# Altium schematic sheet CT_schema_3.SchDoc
size 297 x 271 mm
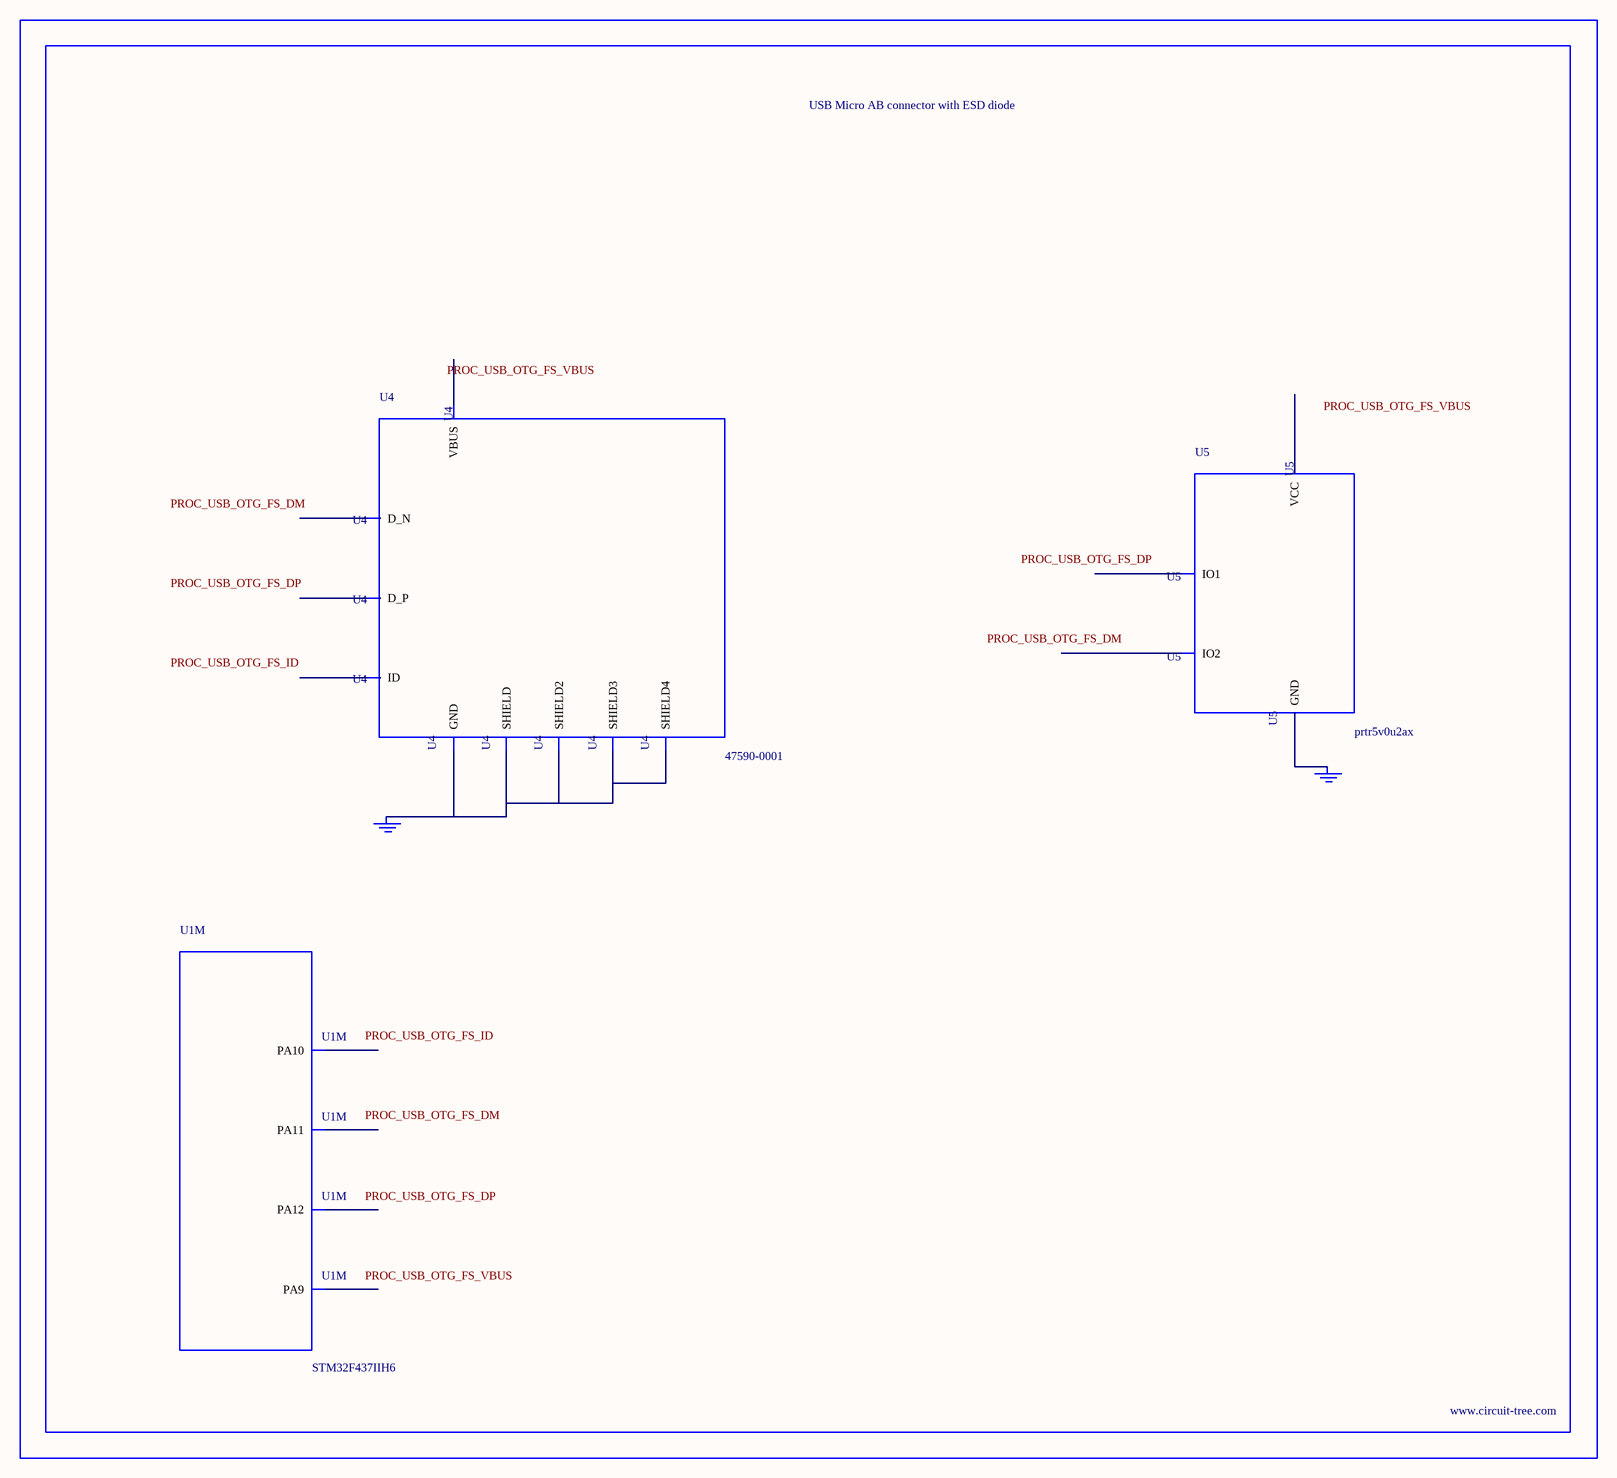
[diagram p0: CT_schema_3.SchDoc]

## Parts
BORDER2  (no value)
GND_INSTANCE_2_0  (no value)
GND_INSTANCE_2_1  (no value)
U1  STM32F437IIH6  [UFBGA176_25]  (part M of 15)
U4  47590-0001  [MICRO_USB_AB]
U5  prtr5v0u2ax  [SOT143B]

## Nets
NetGND_INSTANCE_2_0_0: GND_INSTANCE_2_0.0(GND) U4.5(GND) U4.6(SHIELD) U4.7(SHIELD2) U4.8(SHIELD3) U4.9(SHIELD4)
NetGND_INSTANCE_2_1_0: GND_INSTANCE_2_1.0(GND) U5.1(GND)

Not connected (* = marked no-connect by the designer): U1 B15(PA12) C15(PA11) D15(PA10) E15(PA9); U4 1(VBUS) 2(D_N) 3(D_P) 4(ID); U5 2(IO1) 3(IO2) 4(VCC)

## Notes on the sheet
- Labels drawn without touching a wire or pin: PROC_USB_OTG_FS_DM, PROC_USB_OTG_FS_DP, PROC_USB_OTG_FS_ID, PROC_USB_OTG_FS_VBUS

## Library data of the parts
BORDER2 = BORDER_PAGE2
GND_INSTANCE_2_0 GND_INSTANCE_2_1 = GND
